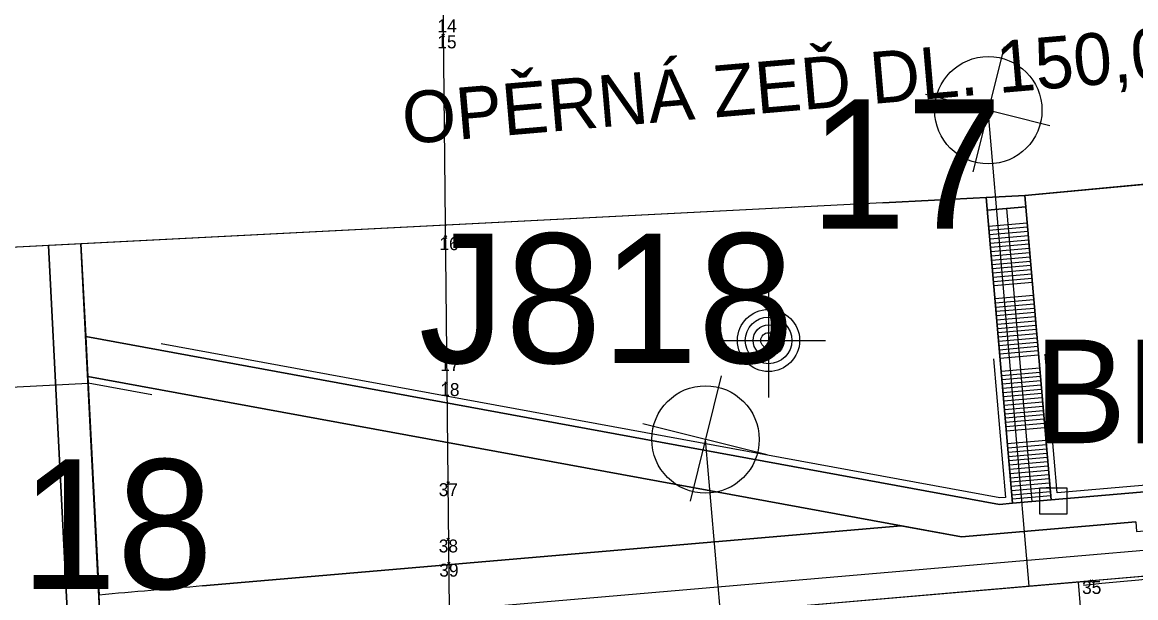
# Model space of a CAD drawing. Extents: x -606444 to -604546, y -1158114 to -1156869.
# Drawn here: x -606032.4 to -605946.4, y -1157296.9 to -1157252.5 of the extents above; entities that cross this region are included whole.
import ezdxf

# ---------------------------------------------------------------- set-up
doc = ezdxf.new("R2010")
doc.units = 0
for name, color, linetype in [('0_sondy', 7, 'Continuous'), ('ARCHIVNÍ SONDY', 7, 'Continuous'), ('B_CHOD', 7, 'Continuous'), ('B_TRAM', 7, 'Continuous'), ('B_VOZ', 7, 'Continuous'), ('B_ZELEN', 7, 'Continuous'), ('geofyzikální profily_předběžný GTP', 7, 'Continuous'), ('korozní průzkum', 7, 'Continuous'), ('netisk', 7, 'Continuous'), ('NS_VB', 7, 'Continuous'), ('NS_VB_OBJ', 7, 'Continuous'), ('NS_VB_POP', 7, 'Continuous'), ('NS_VB_SVAHY', 7, 'Continuous'), ('OSA', 7, 'Continuous'), ('podélný profil trasou tramvaje', 7, 'Continuous'), ('sondy předběžného průzkumu', 7, 'Continuous')]:
    doc.layers.add(name, color=color, linetype=linetype)

# ---------------------------------------------------------------- blocks, each defined once
blk = doc.blocks.new('709')
for p, q in [((0, 2.2), (0, -2.2)), ((-2.2, 0), (2.2, 0))]:
    blk.add_line(p, q)
for radius in [1.2, 0.9, 0.6, 0.3]:
    blk.add_circle((0, 0), radius)
blk = doc.blocks.new('IG vrt archivní')
at = {"layer": 'sondy předběžného průzkumu'}
for p, q in [((0.406, 1.636), (-0.393, -1.584)), ((1.589, -0.397), (-1.612, 0.402))]:
    blk.add_line(p, q, dxfattribs=at)
blk.add_circle((0.001, 0.002), 1.382, dxfattribs=at)

msp = doc.modelspace()

# ---------------------------------------------------------------- linework, layer by layer
for p, q in [((-605999.9, -1157253.482), (-606000, -1157253.382)), ((-605999.9, -1157253.482), (-606000, -1157253.582)), ((-605999.9, -1157253.482), (-605999.8, -1157253.382)), ((-605999.9, -1157253.482), (-605999.8, -1157253.582)), ((-605999.712, -1157269.06), (-605999.812, -1157268.96)), ((-605999.712, -1157269.06), (-605999.812, -1157269.16)), ((-605999.712, -1157269.06), (-605999.612, -1157268.96)), ((-605999.712, -1157269.06), (-605999.612, -1157269.16)), ((-605999.676, -1157278.397), (-605999.776, -1157278.297)), ((-605999.676, -1157278.397), (-605999.776, -1157278.497)), ((-605999.676, -1157278.397), (-605999.576, -1157278.297)), ((-605999.676, -1157278.397), (-605999.576, -1157278.497)), ((-605999.673, -1157280.321), (-605999.773, -1157280.221)), ((-605999.673, -1157280.321), (-605999.773, -1157280.421)), ((-605999.673, -1157280.321), (-605999.573, -1157280.221)), ((-605999.673, -1157280.321), (-605999.573, -1157280.421)), ((-605999.509, -1157288.05), (-605999.609, -1157287.95)), ((-605999.509, -1157288.05), (-605999.609, -1157288.15)), ((-605999.509, -1157288.05), (-605999.409, -1157287.95)), ((-605999.509, -1157288.05), (-605999.409, -1157288.15)), ((-605999.506, -1157292.398), (-605999.606, -1157292.298)), ((-605999.506, -1157292.398), (-605999.406, -1157292.298)), ((-605999.506, -1157292.398), (-605999.606, -1157292.498)), ((-605999.506, -1157292.398), (-605999.406, -1157292.498)), ((-605999.461, -1157294.267), (-605999.561, -1157294.167)), ((-605999.461, -1157294.267), (-605999.561, -1157294.367)), ((-605999.461, -1157294.267), (-605999.361, -1157294.167)), ((-605999.461, -1157294.267), (-605999.361, -1157294.367)), ((-605949.822, -1157295.602), (-605949.922, -1157295.502)), ((-605949.822, -1157295.602), (-605949.922, -1157295.702)), ((-605949.822, -1157295.602), (-605949.722, -1157295.502)), ((-605949.822, -1157295.602), (-605949.722, -1157295.702))]:
    msp.add_line(p, q)
at = {"layer": 'B_CHOD'}
for p, q in [((-606027.873, -1157269.569), (-606030.37, -1157269.696)), ((-606030.37, -1157269.696), (-606027.291, -1157329.892)), ((-606024.795, -1157329.75), (-606027.873, -1157269.569))]:
    msp.add_line(p, q, dxfattribs=at)
for points in [[(-605957.964, -1157266.003), (-605955.932, -1157289.599), (-605952.943, -1157289.341), (-605954.966, -1157265.85), (-605957.964, -1157266.003)], [(-605897.784, -1157284.592), (-605952.943, -1157289.341), (-605955.932, -1157289.599), (-605956.929, -1157289.684), (-606027.507, -1157276.731), (-606027.349, -1157279.81), (-605959.865, -1157292.196), (-605946.41, -1157291.037), (-605946.346, -1157291.784), (-605902.508, -1157288.01), (-605902.572, -1157287.263), (-605897.591, -1157286.834), (-605897.784, -1157284.592)]]:
    msp.add_lwpolyline(points, dxfattribs=at)
at = {"layer": 'B_TRAM'}
for p, q in [((-606018.476, -1157295.987), (-605964.518, -1157291.342)), ((-605964.518, -1157291.342), (-605959.865, -1157292.196)), ((-605959.865, -1157292.196), (-605946.41, -1157291.037)), ((-605946.41, -1157291.037), (-605946.346, -1157291.784)), ((-606025.923, -1157307.684), (-606026.469, -1157296.689))]:
    msp.add_line(p, q, dxfattribs=at)
msp.add_arc((-605876.247, -1158963.441), 1673.509, 94.875347, 95.15007, dxfattribs=at)
at = {"layer": 'B_VOZ'}
for p, q in [((-606030.37, -1157269.696), (-606036.362, -1157270.002)), ((-606027.291, -1157329.892), (-606030.37, -1157269.696))]:
    msp.add_line(p, q, dxfattribs=at)
at = {"layer": 'B_ZELEN'}
for points in [[(-605896.3, -1157260.32), (-605954.966, -1157265.85), (-605952.943, -1157289.341), (-605897.784, -1157284.592), (-605896.668, -1157297.544), (-605951.828, -1157302.293), (-605950.029, -1157323.188), (-605891.821, -1157318.079), (-605892.14, -1157311.81), (-605892.72, -1157300.84), (-605893.25, -1157290.57), (-605893.57, -1157284.85), (-605895.26, -1157280.16), (-605896.88, -1157277.8), (-605897.04, -1157273.82), (-605896.3, -1157260.32)], [(-605965.953, -1157266.41), (-606027.873, -1157269.569), (-606027.507, -1157276.731), (-605956.929, -1157289.684), (-605955.932, -1157289.599), (-605957.964, -1157266.003), (-605965.953, -1157266.41)], [(-606027.349, -1157279.81), (-606026.469, -1157296.689)], [(-606018.476, -1157295.987), (-605964.518, -1157291.342), (-606027.349, -1157279.81)]]:
    msp.add_lwpolyline(points, dxfattribs=at)
msp.add_arc((-605876.247, -1158963.441), 1673.509, 94.875347, 95.15007, dxfattribs=at)
at = {"layer": 'geofyzikální profily_předběžný GTP'}
msp.add_lwpolyline([(-606000.25, -1157218.24), (-605999.1, -1157330.17)], dxfattribs=at)
msp.add_spline([(-605950.45, -1157295.92), (-605904.874, -1157291.719), (-605856.97, -1157287.385), (-605826.739, -1157281.637), (-605800.72, -1157271.737), (-605782.37, -1157261.31), (-605766.27, -1157249.354), (-605744.492, -1157228.624), (-605716.536, -1157200.554), (-605701.175, -1157186.191), (-605682.489, -1157172.855), (-605668.895, -1157164.852), (-605653.702, -1157158.019), (-605640.639, -1157153.348), (-605624.44, -1157148.581)], degree=3, dxfattribs=at)
at = {"layer": 'korozní průzkum'}
msp.add_lwpolyline([(-605953.81, -1157288.408), (-605951.729, -1157288.408), (-605951.729, -1157290.445), (-605953.81, -1157290.445)], close=True, dxfattribs=at)
at = {"layer": 'netisk'}
for p, q in [((-605954.636, -1157296.011), (-605957.8, -1157259.262)), ((-605978.488, -1157298.065), (-605979.64, -1157284.682)), ((-605950.86, -1157295.686), (-605950.572, -1157299.024))]:
    msp.add_line(p, q, dxfattribs=at)
at = {"layer": 'NS_VB'}
for p, q in [((-605954.966, -1157265.85), (-605896.3, -1157260.32)), ((-605965.953, -1157266.41), (-606038.859, -1157270.129)), ((-605965.953, -1157266.41), (-605954.966, -1157265.85)), ((-605957.964, -1157266.003), (-605955.932, -1157289.599)), ((-605954.966, -1157265.85), (-605952.943, -1157289.341)), ((-606030.37, -1157269.696), (-606027.291, -1157329.892)), ((-606027.873, -1157269.569), (-606024.794, -1157329.765)), ((-605956.929, -1157289.684), (-606027.507, -1157276.731)), ((-605959.865, -1157292.196), (-606027.349, -1157279.81)), ((-605897.784, -1157284.592), (-605956.929, -1157289.684)), ((-605946.41, -1157291.037), (-605959.865, -1157292.196))]:
    msp.add_line(p, q, dxfattribs=at)
for points in [[(-606022.405, -1157281.226), (-606027.323, -1157280.323)], [(-605964.518, -1157291.342), (-606018.476, -1157295.987)]]:
    msp.add_lwpolyline(points, dxfattribs=at)
for centre, radius, start, end in [((-605876.247, -1158963.441), 1673.509, 94.875347, 95.15007), ((-605976.066, -1157855.921), 561.5, 95.15007, 95.15175)]:
    msp.add_arc(centre, radius, start, end, dxfattribs=at)
at = {"layer": 'NS_VB_OBJ'}
for points in [[(-605957.395, -1157278.443), (-605956.473, -1157289.143), (-605956.904, -1157289.18), (-606021.683, -1157277.291)], [(-605897.827, -1157284.094), (-605952.488, -1157288.8), (-605953.409, -1157278.1)], [(-606038.309, -1157280.885), (-606027.323, -1157280.323)]]:
    msp.add_lwpolyline(points, dxfattribs=at)
at = {"layer": 'NS_VB_SVAHY'}
for p, q in [((-605957.88, -1157266.977), (-605954.892, -1157266.709)), ((-605954.892, -1157266.709), (-605957.88, -1157266.977)), ((-605956.386, -1157266.842), (-605954.438, -1157289.47)), ((-605957.775, -1157268.198), (-605954.786, -1157267.94)), ((-605957.747, -1157268.527), (-605954.758, -1157268.269)), ((-605957.718, -1157268.855), (-605954.729, -1157268.598)), ((-605957.69, -1157269.184), (-605954.701, -1157268.927)), ((-605957.662, -1157269.513), (-605954.673, -1157269.256)), ((-605957.633, -1157269.842), (-605954.644, -1157269.584)), ((-605957.605, -1157270.171), (-605954.616, -1157269.913)), ((-605957.577, -1157270.499), (-605954.588, -1157270.242)), ((-605957.548, -1157270.828), (-605954.559, -1157270.571)), ((-605957.52, -1157271.157), (-605954.531, -1157270.9)), ((-605957.492, -1157271.486), (-605954.503, -1157271.228)), ((-605957.463, -1157271.814), (-605954.475, -1157271.557)), ((-605957.435, -1157272.143), (-605954.446, -1157271.886)), ((-605957.407, -1157272.472), (-605954.418, -1157272.215)), ((-605957.379, -1157272.801), (-605954.39, -1157272.543)), ((-605957.293, -1157273.797), (-605954.304, -1157273.54)), ((-605957.264, -1157274.126), (-605954.275, -1157273.869)), ((-605957.236, -1157274.455), (-605954.247, -1157274.197)), ((-605957.208, -1157274.783), (-605954.219, -1157274.526)), ((-605957.18, -1157275.112), (-605954.191, -1157274.855)), ((-605957.151, -1157275.441), (-605954.162, -1157275.184)), ((-605957.123, -1157275.77), (-605954.134, -1157275.512)), ((-605957.095, -1157276.099), (-605954.106, -1157275.841)), ((-605957.066, -1157276.427), (-605954.077, -1157276.17)), ((-605957.038, -1157276.756), (-605954.049, -1157276.499)), ((-605957.01, -1157277.085), (-605954.021, -1157276.828)), ((-605956.981, -1157277.414), (-605953.992, -1157277.156)), ((-605956.953, -1157277.743), (-605953.964, -1157277.485)), ((-605956.925, -1157278.071), (-605953.936, -1157277.814)), ((-605956.896, -1157278.4), (-605953.907, -1157278.143)), ((-605956.811, -1157279.396), (-605953.822, -1157279.139)), ((-605956.782, -1157279.725), (-605953.793, -1157279.468)), ((-605956.754, -1157280.054), (-605953.765, -1157279.797)), ((-605956.726, -1157280.383), (-605953.737, -1157280.125)), ((-605956.697, -1157280.712), (-605953.708, -1157280.454)), ((-605956.669, -1157281.04), (-605953.68, -1157280.783)), ((-605956.641, -1157281.369), (-605953.652, -1157281.112)), ((-605956.612, -1157281.698), (-605953.624, -1157281.441)), ((-605956.584, -1157282.027), (-605953.595, -1157281.769)), ((-605956.556, -1157282.355), (-605953.567, -1157282.098)), ((-605956.528, -1157282.684), (-605953.539, -1157282.427)), ((-605956.499, -1157283.013), (-605953.51, -1157282.756)), ((-605956.471, -1157283.342), (-605953.482, -1157283.084)), ((-605956.443, -1157283.671), (-605953.454, -1157283.413)), ((-605956.414, -1157283.999), (-605953.425, -1157283.742)), ((-605956.329, -1157284.996), (-605953.34, -1157284.738)), ((-605956.3, -1157285.324), (-605953.311, -1157285.067)), ((-605956.272, -1157285.653), (-605953.283, -1157285.396)), ((-605956.244, -1157285.982), (-605953.255, -1157285.725)), ((-605956.215, -1157286.311), (-605953.226, -1157286.053)), ((-605956.187, -1157286.64), (-605953.198, -1157286.382)), ((-605956.159, -1157286.968), (-605953.17, -1157286.711)), ((-605956.13, -1157287.297), (-605953.141, -1157287.04)), ((-605956.102, -1157287.626), (-605953.113, -1157287.369)), ((-605956.074, -1157287.955), (-605953.085, -1157287.697)), ((-605956.045, -1157288.284), (-605953.057, -1157288.026)), ((-605956.017, -1157288.612), (-605953.028, -1157288.355)), ((-605955.989, -1157288.941), (-605953, -1157288.684)), ((-605955.961, -1157289.27), (-605952.972, -1157289.013)), ((-605955.932, -1157289.599), (-605952.943, -1157289.341))]:
    msp.add_line(p, q, dxfattribs=at)
at = {"layer": 'OSA'}
msp.add_line((-605877.412, -1157289.362), (-606018.006, -1157301.467), dxfattribs=at)
msp.add_lwpolyline([(-605877.584, -1157287.369), (-606018.177, -1157299.475)], dxfattribs=at)
at = {"layer": 'podélný profil trasou tramvaje'}
for points in [[(-605949.772, -1157295.552), (-605894.77, -1157290.856), (-605875.375, -1157288.893), (-605864.92, -1157286.84), (-605852.13, -1157285.48)], [(-605949.822, -1157295.602), (-605999.995, -1157299.904), (-606029.31, -1157302.594), (-606037.052, -1157303.307), (-606055.199, -1157306.006), (-606073.753, -1157309.948), (-606079.242, -1157312.228), (-606082.046, -1157313.334), (-606094.925, -1157318.61), (-606110.15, -1157327.53), (-606116.44, -1157331.17), (-606138.24, -1157349.34), (-606153.99, -1157367.55), (-606162.8, -1157380.7), (-606171.56, -1157397.75), (-606180.53, -1157420.69), (-606192.65, -1157452.3), (-606195.209, -1157458.765), (-606195.209, -1157458.765), (-606195.33, -1157460.2), (-606196.07, -1157462.31), (-606197.75, -1157467.6), (-606193.13, -1157485.08)]]:
    msp.add_lwpolyline(points, dxfattribs=at)

# ---------------------------------------------------------------- block references
at = {"layer": '0_sondy', "xscale": 2, "yscale": 2}
msp.add_blockref('709', (-605974.767, -1157277.033), dxfattribs=at)
at = {"layer": 'ARCHIVNÍ SONDY', "xscale": 3, "yscale": 3}
for p in [(-605957.8, -1157259.262), (-605979.64, -1157284.682)]:
    msp.add_blockref('IG vrt archivní', p, dxfattribs=at)

# ---------------------------------------------------------------- texts
for s, p in [('14', (-606000.338, -1157253.243)), ('15', (-606000.349, -1157254.482)), ('16', (-606000.188, -1157270.06)), ('17', (-606000.125, -1157279.397)), ('18', (-606000.122, -1157281.321)), ('37', (-606000.241, -1157289.05)), ('38', (-606000.238, -1157293.398)), ('39', (-606000.197, -1157295.267)), ('35', (-605950.554, -1157296.602))]:
    msp.add_text(s, height=1).set_placement(p)
at = {"layer": '0_sondy'}
for s, p in [('17', (-605971.581, -1157268.408)), ('18', (-606032.544, -1157296.213))]:
    msp.add_text(s, height=10, dxfattribs=at).set_placement(p)
at = {"layer": 'ARCHIVNÍ SONDY'}
msp.add_text('J818', height=10, dxfattribs=at).set_placement((-606001.789, -1157278.776))
at = {"layer": 'korozní průzkum'}
msp.add_text('BP8', height=8, dxfattribs=at).set_placement((-605954.271, -1157284.961))
at = {"layer": 'NS_VB_POP'}
msp.add_text('OPĚRNÁ ZEĎ DL. 150,00 m', height=4, rotation=4.92107, dxfattribs=at).set_placement((-606002.891, -1157261.89))

doc.saveas('drawing.dxf')
